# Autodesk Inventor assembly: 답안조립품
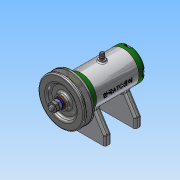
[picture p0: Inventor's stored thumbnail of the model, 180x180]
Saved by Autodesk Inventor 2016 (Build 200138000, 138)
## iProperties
Created: 2018-05
Part Number: 답안조립품
Material: 일반
Document SubType Name: Assembly
Designer: Administrator
Author: Administrator
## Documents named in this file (16)
- C:\Users\Administrator\Desktop\480507V1019\답안조립품.iam
- C:\Users\Administrator\Desktop\480507V1019\본체.ipt
- C:\Users\Administrator\Desktop\480507V1019\뒤커버.ipt
- C:\Users\Administrator\Desktop\480507V1019\베어링 6002.ipt
- C:\Users\Administrator\Desktop\480507V1019\볼트 M4x12.ipt
- C:\Users\Administrator\Desktop\480507V1019\축.ipt
- C:\Users\Administrator\Desktop\480507V1019\키 3x3x12.ipt
- C:\Users\Administrator\Desktop\480507V1019\앞커버.ipt
- C:\Users\Administrator\Desktop\480507V1019\오일 실 15 25 7.ipt
- C:\Users\Administrator\Desktop\480507V1019\니플 M6x0.75.ipt
- C:\Users\Administrator\Desktop\480507V1019\V벨트풀리.ipt
- C:\Users\Administrator\Desktop\480507V1019\와셔 8x17.ipt
- C:\Users\Administrator\Desktop\480507V1019\스프링와셔 8.ipt
- C:\Users\Administrator\Desktop\480507V1019\너트 M8.ipt
- C:\Users\Administrator\Desktop\480507V1019\와셔 6x11.5.ipt
- C:\Users\Administrator\Desktop\480507V1019\볼트 M6x8.ipt
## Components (1 placed, 1 different names)
1. V벨트풀리:1
